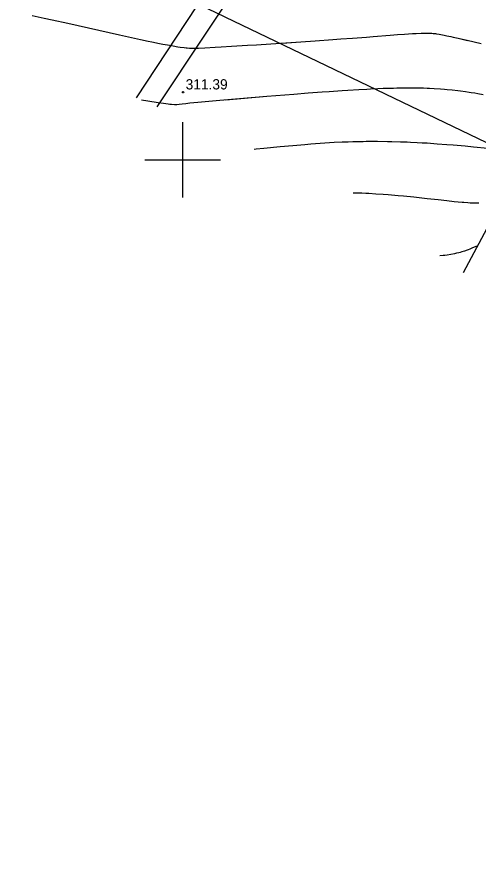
# Model space of a CAD drawing. Extents: x 7477803 to 7478145, y 5500698 to 5500984.
# Drawn here: x 7477839 to 7477869.5, y 5500753.5 to 5500809.5 of the extents above; entities that cross this region are included whole.
import ezdxf

# ---------------------------------------------------------------- set-up
doc = ezdxf.new("R2010")
doc.units = 0
for name, color, linetype in [('eWN', 7, 'Continuous'), ('gr_dzialki', 7, 'Continuous'), ('pkt_wys', 7, 'Continuous'), ('robocza49', 7, 'Continuous'), ('skarpa_gora', 7, 'Continuous'), ('warst_ciagla', 7, 'Continuous'), ('warst_przeryw', 7, 'Continuous'), ('zakresy', 7, 'Continuous')]:
    doc.layers.add(name, color=color, linetype=linetype)

# ---------------------------------------------------------------- blocks, each defined once
blk = doc.blocks.new('801_3')
at = {"layer": 'pkt_wys'}
blk.add_circle((0, 0), 0.045, dxfattribs=at)
blk.add_circle((0, 0), 0.045, dxfattribs=at)

msp = doc.modelspace()

# ---------------------------------------------------------------- linework, layer by layer
at = {"layer": 'eWN'}
msp.add_lwpolyline([(7477846.934, 5500804.11), (7477862.957, 5500828.422)], dxfattribs=at)
at = {"layer": 'gr_dzialki'}
msp.add_lwpolyline([(7477876.54, 5500846.03), (7477848.298, 5500803.51)], dxfattribs=at)
at = {"layer": 'robocza49'}
for p, q in [((7477850, 5500797.5), (7477850, 5500802.5)), ((7477847.5, 5500800), (7477852.5, 5500800))]:
    msp.add_line(p, q, dxfattribs=at)
at = {"layer": 'skarpa_gora'}
msp.add_lwpolyline([(7477896.354, 5500816.303), (7477887.581, 5500819.233), (7477880.086, 5500814.385), (7477872.402, 5500799.706), (7477868.556, 5500792.528)], dxfattribs=at)
at = {"layer": 'warst_ciagla'}
for points in [[(7477840.042, 5500809.555), (7477840.842, 5500809.385), (7477841.362, 5500809.273), (7477842.395, 5500809.045), (7477845.823, 5500808.269), (7477846.814, 5500808.051), (7477847.219, 5500807.964), (7477847.725, 5500807.858), (7477847.963, 5500807.809), (7477848.464, 5500807.708), (7477848.696, 5500807.664), (7477848.986, 5500807.609), (7477849.122, 5500807.584), (7477849.379, 5500807.539), (7477849.688, 5500807.489), (7477849.827, 5500807.468), (7477850.106, 5500807.43), (7477850.227, 5500807.417), (7477850.302, 5500807.41), (7477850.443, 5500807.399), (7477850.509, 5500807.396), (7477850.639, 5500807.392), (7477850.77, 5500807.392), (7477851.057, 5500807.399), (7477851.459, 5500807.416), (7477852.14, 5500807.451), (7477852.544, 5500807.474), (7477853.227, 5500807.514), (7477854.284, 5500807.58), (7477854.875, 5500807.618), (7477855.831, 5500807.681), (7477857.822, 5500807.816), (7477858.763, 5500807.881), (7477859.928, 5500807.964), (7477860.472, 5500808.003), (7477861.239, 5500808.059), (7477862.17, 5500808.129), (7477862.597, 5500808.163), (7477863.73, 5500808.253), (7477864.223, 5500808.29), (7477864.674, 5500808.322), (7477865.211, 5500808.354), (7477865.451, 5500808.365), (7477865.777, 5500808.377), (7477865.909, 5500808.381), (7477866.072, 5500808.383), (7477866.148, 5500808.383), (7477866.306, 5500808.382), (7477866.492, 5500808.375), (7477866.583, 5500808.369), (7477866.725, 5500808.353), (7477866.803, 5500808.343), (7477866.979, 5500808.314), (7477867.313, 5500808.251), (7477867.489, 5500808.215), (7477867.751, 5500808.159), (7477867.893, 5500808.128), (7477868.24, 5500808.05), (7477868.848, 5500807.909)], [(7477856.573, 5500807.731), (7477857.822, 5500807.816), (7477858.763, 5500807.881), (7477859.928, 5500807.964), (7477860.472, 5500808.003), (7477861.239, 5500808.059), (7477862.17, 5500808.129), (7477862.597, 5500808.163), (7477863.73, 5500808.253), (7477864.223, 5500808.29), (7477864.674, 5500808.322), (7477865.211, 5500808.354), (7477865.451, 5500808.365), (7477865.777, 5500808.377), (7477865.909, 5500808.381), (7477866.072, 5500808.383), (7477866.148, 5500808.383), (7477866.306, 5500808.382), (7477866.492, 5500808.375), (7477866.583, 5500808.369), (7477866.725, 5500808.353), (7477866.803, 5500808.343), (7477866.979, 5500808.314), (7477867.313, 5500808.251), (7477867.489, 5500808.215), (7477867.751, 5500808.159), (7477867.893, 5500808.128), (7477868.24, 5500808.05), (7477868.834, 5500807.912), (7477869.76, 5500807.69)], [(7477870.2, 5500800.757), (7477869.239, 5500800.845), (7477868.691, 5500800.894), (7477867.896, 5500800.962), (7477867.477, 5500800.996), (7477866.829, 5500801.046), (7477866.169, 5500801.092), (7477865.838, 5500801.112), (7477865.508, 5500801.13), (7477865.069, 5500801.152), (7477864.85, 5500801.161), (7477864.413, 5500801.177), (7477863.834, 5500801.193), (7477863.545, 5500801.198), (7477862.898, 5500801.205), (7477862.576, 5500801.205), (7477862.148, 5500801.203), (7477861.935, 5500801.2), (7477861.51, 5500801.192), (7477860.945, 5500801.176), (7477860.664, 5500801.165), (7477860.034, 5500801.136), (7477859.721, 5500801.118), (7477859.099, 5500801.078), (7477858.484, 5500801.032), (7477858.081, 5500801), (7477857.293, 5500800.932), (7477856.443, 5500800.854), (7477855.369, 5500800.751), (7477854.859, 5500800.699), (7477854.72, 5500800.684)], [(7477862.404, 5500801.205), (7477862.139, 5500801.203), (7477861.785, 5500801.198), (7477861.609, 5500801.194), (7477861.257, 5500801.186), (7477860.789, 5500801.17), (7477860.557, 5500801.161), (7477860.034, 5500801.136), (7477859.721, 5500801.118), (7477859.099, 5500801.078), (7477858.484, 5500801.032), (7477858.081, 5500801), (7477857.293, 5500800.932), (7477856.443, 5500800.854), (7477855.369, 5500800.751), (7477854.859, 5500800.699), (7477854.72, 5500800.684)], [(7477869.445, 5500794.289), (7477869.36, 5500794.246), (7477869.187, 5500794.165), (7477869.012, 5500794.091), (7477868.894, 5500794.045), (7477868.815, 5500794.016), (7477868.656, 5500793.962), (7477868.476, 5500793.906), (7477868.355, 5500793.872), (7477868.275, 5500793.85), (7477868.113, 5500793.811), (7477867.991, 5500793.784), (7477867.747, 5500793.736), (7477867.503, 5500793.696), (7477867.34, 5500793.674), (7477867.232, 5500793.661), (7477867.017, 5500793.639)]]:
    msp.add_lwpolyline(points, dxfattribs=at)
at = {"layer": 'warst_przeryw'}
for points in [[(7477865.802, 5500804.74), (7477865.561, 5500804.744), (7477865.224, 5500804.747), (7477865.049, 5500804.747), (7477864.686, 5500804.745), (7477864.174, 5500804.737), (7477863.906, 5500804.73), (7477863.275, 5500804.711), (7477862.922, 5500804.697), (7477862.433, 5500804.675), (7477862.181, 5500804.663), (7477861.662, 5500804.636), (7477860.938, 5500804.594), (7477860.563, 5500804.57), (7477859.686, 5500804.511), (7477859.232, 5500804.478), (7477858.3, 5500804.407), (7477857.362, 5500804.333), (7477855.565, 5500804.184), (7477852.456, 5500803.921), (7477851.73, 5500803.857), (7477851.005, 5500803.792), (7477850.745, 5500803.768), (7477850.478, 5500803.741), (7477850.211, 5500803.709), (7477849.958, 5500803.677), (7477849.766, 5500803.656), (7477849.618, 5500803.646), (7477849.458, 5500803.644), (7477849.271, 5500803.651), (7477849.152, 5500803.662), (7477849.037, 5500803.677), (7477848.736, 5500803.721), (7477848.375, 5500803.779), (7477847.701, 5500803.888), (7477847.281, 5500803.957)], [(7477869.888, 5500804.312), (7477869.522, 5500804.374), (7477869.338, 5500804.404), (7477869.091, 5500804.441), (7477868.967, 5500804.46), (7477868.718, 5500804.495), (7477868.384, 5500804.539), (7477868.216, 5500804.56), (7477867.835, 5500804.604), (7477867.494, 5500804.639), (7477867.32, 5500804.656), (7477867.053, 5500804.678), (7477866.634, 5500804.707), (7477866.338, 5500804.722), (7477866.183, 5500804.729), (7477865.944, 5500804.736), (7477865.692, 5500804.742), (7477865.34, 5500804.746), (7477865.156, 5500804.747), (7477864.773, 5500804.746), (7477864.232, 5500804.738), (7477863.947, 5500804.731), (7477863.275, 5500804.711), (7477862.922, 5500804.697), (7477862.433, 5500804.675), (7477862.181, 5500804.663), (7477861.662, 5500804.636), (7477860.938, 5500804.594), (7477860.563, 5500804.57), (7477859.686, 5500804.511), (7477859.232, 5500804.478), (7477858.3, 5500804.407), (7477857.362, 5500804.333), (7477855.565, 5500804.184), (7477852.845, 5500803.954)], [(7477869.593, 5500797.135), (7477869.468, 5500797.133), (7477869.221, 5500797.135), (7477869.015, 5500797.141), (7477868.88, 5500797.147), (7477868.615, 5500797.164), (7477868.484, 5500797.175), (7477868.225, 5500797.198), (7477867.971, 5500797.225), (7477867.47, 5500797.282), (7477866.916, 5500797.346), (7477866.189, 5500797.426), (7477865.832, 5500797.464), (7477865.302, 5500797.518), (7477864.608, 5500797.586), (7477864.266, 5500797.618), (7477863.595, 5500797.677), (7477863.267, 5500797.703), (7477862.786, 5500797.737), (7477862.32, 5500797.763), (7477862.118, 5500797.772), (7477861.854, 5500797.782), (7477861.724, 5500797.786), (7477861.436, 5500797.792), (7477861.29, 5500797.793)]]:
    msp.add_lwpolyline(points, dxfattribs=at)
at = {"layer": 'zakresy'}
msp.add_lwpolyline([(7477995.059, 5500962.348), (7477983.951, 5500968.084), (7477970.781, 5500968.613), (7477936.09, 5500958.171), (7477930.511, 5500954.336), (7477914.305, 5500958.58), (7477904.32, 5500957.41), (7477897.265, 5500950.868), (7477811.424, 5500829.338), (7477936.003, 5500769.492), (7478008.982, 5500726.585), (7478019.402, 5500721.781), (7478037.95, 5500734.97), (7478039.493, 5500755.094), (7478043.98, 5500765.708), (7478067.545, 5500795.068), (7478092.109, 5500820.25), (7478076.156, 5500837.989), (7478068.105, 5500851.146), (7478061.422, 5500873.298), (7478054.135, 5500876.371), (7478039.669, 5500897.644), (7478026.36, 5500915.23), (7478015.054, 5500927.728)], close=True, dxfattribs=at)

# ---------------------------------------------------------------- block references
at = {"layer": 'pkt_wys', "rotation": 0.0626175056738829}
msp.add_blockref('801_3', (7477850.027, 5500804.472), dxfattribs=at)

# ---------------------------------------------------------------- texts
at = {"layer": 'pkt_wys'}
msp.add_text('311.39', height=0.68, rotation=0.0626, dxfattribs=at).set_placement((7477850.196, 5500804.656))

doc.saveas('drawing.dxf')
